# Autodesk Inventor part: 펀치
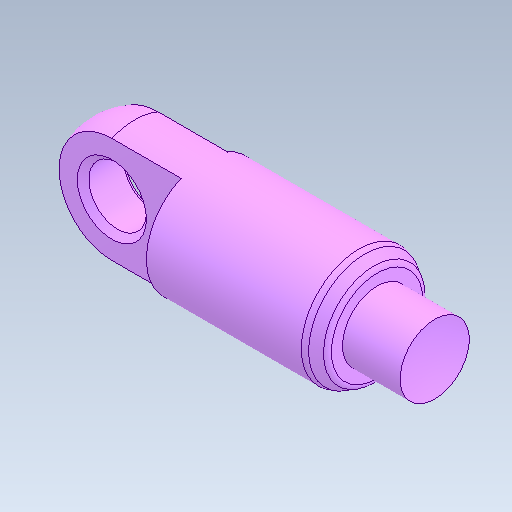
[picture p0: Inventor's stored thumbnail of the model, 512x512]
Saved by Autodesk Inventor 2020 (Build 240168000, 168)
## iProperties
Created: 2024-08
Part Number: 펀치
Material: 강철, 합금
Document SubType Name: Modeling
Designer: oem
Density: 7.73 g/cm^3
Appearance: 기본값
Author: jhkim
Sending System: Autodesk Inventor 2025
Preprocessor: ST-DEVELOPER v20
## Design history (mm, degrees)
node "펀치1"
node "솔리드2"
node "솔리드1"
